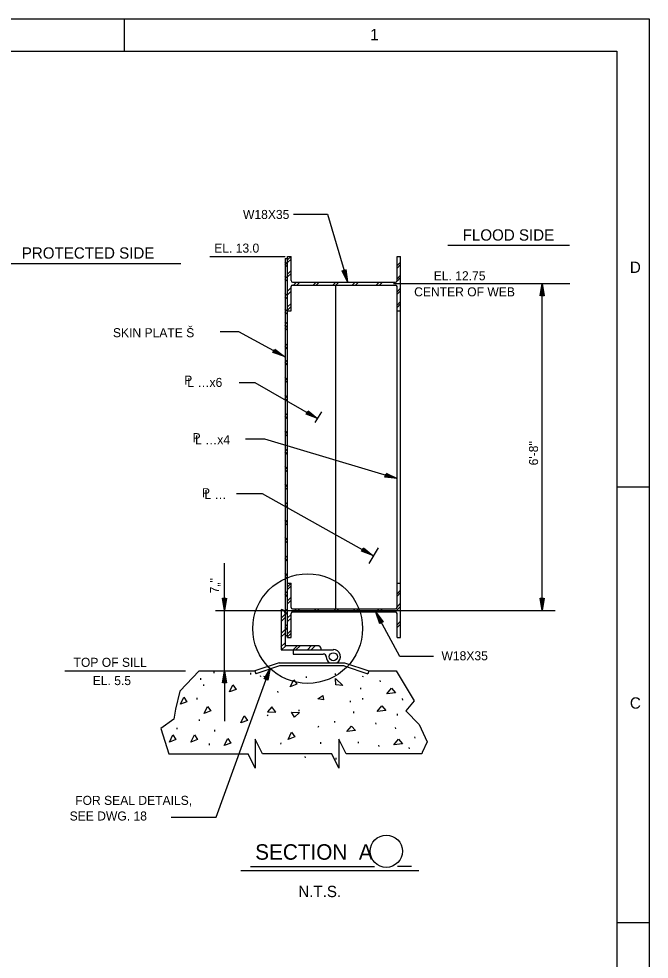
# Model space of a CAD drawing. Extents: x 0 to 53.3, y -0.3 to 37.1.
# Drawn here: x 40.32 to 53.33, y 17.66 to 37.08 of the extents above; entities that cross this region are included whole.
import ezdxf

# ---------------------------------------------------------------- set-up
doc = ezdxf.new("R2010")
doc.units = 0
for name, color, linetype in [('Level 1', 7, 'Continuous'), ('Level 2', 7, 'Continuous'), ('Level 3', 7, 'Continuous'), ('Level 44', 7, 'Continuous'), ('Level 50', 7, 'Continuous')]:
    doc.layers.add(name, color=color, linetype=linetype)

msp = doc.modelspace()

# ---------------------------------------------------------------- linework, layer by layer
at = {"layer": 'Level 1'}
for p, q in [((42.5, 36.417), (42.5, 37.083)), ((52.667, 27.417), (53.333, 27.417)), ((44.355, 23.57), (44.355, 23.6)), ((45.106, 23.543), (45.106, 23.573)), ((45.315, 23.491), (45.306, 23.512)), ((45.382, 23.491), (45.391, 23.512)), ((46.858, 23.535), (46.858, 23.563)), ((47.421, 23.491), (47.429, 23.512)), ((44.074, 23.434), (44.074, 23.464)), ((44.137, 23.307), (44.137, 23.337)), ((46.257, 23.47), (46.257, 23.5)), ((47.785, 23.386), (47.781, 23.415)), ((45.676, 23.17), (45.665, 23.194)), ((47.38, 23.235), (47.38, 23.265)), ((44.001, 23.026), (44.001, 23.056)), ((47.169, 22.969), (47.164, 22.998)), ((47.423, 23.023), (47.418, 23.052)), ((48.247, 23.014), (48.243, 23.043)), ((46.108, 22.786), (46.106, 22.808)), ((47.235, 22.745), (47.235, 22.775)), ((48.139, 22.697), (48.134, 22.726)), ((44.047, 22.582), (44.047, 22.612)), ((45.47, 22.686), (45.455, 22.711)), ((46.845, 22.546), (46.845, 22.576)), ((47.694, 22.515), (47.69, 22.544)), ((43.585, 22.41), (43.585, 22.44)), ((44.364, 22.365), (44.364, 22.395)), ((46.5, 22.452), (46.513, 22.479)), ((48.102, 22.416), (48.098, 22.445)), ((47.335, 22.12), (47.335, 22.15)), ((48.501, 22.225), (48.497, 22.254)), ((44.255, 22.084), (44.255, 22.114)), ((45.73, 22.104), (45.732, 22.128)), ((46.556, 22.111), (46.556, 22.141)), ((47.758, 22.053), (47.753, 22.082)), ((48.383, 22.007), (48.379, 22.036)), ((46.238, 21.823), (46.234, 21.846)), ((46.869, 21.788), (46.869, 21.818)), ((52.667, 18.417), (53.333, 18.417))]:
    msp.add_line(p, q, dxfattribs=at)
for points in [[(0, 37.083), (53.333, 37.083), (53.333, -0.25), (0, -0.25)], [(2, 36.417), (52.667, 36.417), (52.667, 0.417), (2, 0.417)], [(44.803, 23.233), (44.666, 23.18), (44.738, 23.327)], [(46.059, 23.339), (45.922, 23.286), (45.994, 23.434)], [(46.866, 23.326), (46.858, 23.46), (47.006, 23.315)], [(47.914, 23.142), (48.013, 23.256), (48.093, 23.162)], [(43.79, 22.978), (43.654, 22.925), (43.726, 23.072)], [(46.612, 23.021), (46.491, 23.037), (46.593, 23.105)], [(44.28, 22.787), (44.143, 22.734), (44.215, 22.882)], [(45.627, 22.765), (45.546, 22.872), (45.456, 22.769)], [(46.116, 22.754), (46.009, 22.659), (45.952, 22.765)], [(47.715, 22.779), (47.814, 22.893), (47.893, 22.799)], [(45.037, 22.594), (44.9, 22.541), (44.972, 22.688)], [(46.016, 22.253), (45.88, 22.2), (45.952, 22.348)], [(47.089, 22.362), (47.188, 22.476), (47.268, 22.382)], [(43.564, 22.197), (43.427, 22.144), (43.499, 22.292)], [(44.008, 22.198), (43.871, 22.145), (43.943, 22.293)], [(44.696, 22.126), (44.56, 22.073), (44.632, 22.22)], [(48.059, 22.09), (48.158, 22.204), (48.238, 22.11)]]:
    msp.add_lwpolyline(points, close=True, dxfattribs=at)
at = {"layer": 'Level 2'}
for p, q in [((51.686, 32.404), (49.177, 32.404)), ((45.815, 32.135), (45.867, 32.135)), ((45.815, 32.135), (45.815, 24.344)), ((45.867, 31.052), (45.867, 32.176)), ((45.867, 32.176), (45.94, 32.176)), ((45.94, 31.676), (45.94, 32.176)), ((48.128, 32.176), (48.201, 32.176)), ((48.128, 31.676), (48.128, 32.176)), ((48.201, 31.052), (48.201, 32.176)), ((48.201, 24.302), (48.201, 32.176)), ((43.663, 32.023), (40.091, 32.023)), ((45.867, 25.426), (45.867, 31.782)), ((45.94, 31.052), (45.94, 31.552)), ((45.971, 31.645), (48.096, 31.645)), ((45.971, 31.583), (48.096, 31.583)), ((46.867, 24.895), (46.867, 31.583)), ((48.128, 31.052), (48.128, 31.552)), ((48.128, 24.926), (48.128, 31.552)), ((45.867, 31.052), (45.94, 31.052)), ((48.128, 31.052), (48.201, 31.052)), ((45.867, 24.302), (45.867, 25.426)), ((45.867, 25.426), (45.94, 25.426)), ((45.94, 24.926), (45.94, 25.426)), ((48.128, 25.426), (48.201, 25.426)), ((48.201, 24.302), (48.201, 25.426)), ((45.732, 24.885), (45.732, 24.053)), ((45.971, 24.895), (48.096, 24.895)), ((45.815, 24.802), (45.815, 24.136)), ((45.94, 24.302), (45.94, 24.802)), ((45.971, 24.833), (48.096, 24.833)), ((48.128, 24.302), (48.128, 24.802)), ((45.815, 24.344), (45.867, 24.344)), ((45.867, 24.302), (45.94, 24.302)), ((48.128, 24.302), (48.201, 24.302)), ((46.481, 24.136), (45.815, 24.136)), ((45.732, 24.053), (46.814, 24.053)), ((45.981, 24.053), (45.981, 23.959)), ((45.981, 23.959), (46.605, 23.959)), ((45.691, 23.782), (45.878, 23.782)), ((47.034, 23.72), (45.701, 23.72)), ((45.878, 23.782), (47.045, 23.782)), ((43.413, 21.904), (45.051, 21.904)), ((46.779, 21.904), (45.35, 21.904)), ((48.638, 21.904), (47.078, 21.904))]:
    msp.add_line(p, q, dxfattribs=at)
msp.add_circle((46.812, 23.908), 0.0833, dxfattribs=at)
for centre, radius, start, end in [((45.971, 31.676), 0.0312, 180, 270), ((48.096, 31.676), 0.0312, 270, 0), ((45.971, 31.552), 0.0312, 90, 180), ((48.096, 31.552), 0.0312, 0, 90), ((45.732, 24.802), 0.0833, 0, 90), ((45.971, 24.926), 0.0312, 180, 270), ((48.096, 24.926), 0.0312, 270, 0), ((45.971, 24.802), 0.0312, 90, 180), ((48.096, 24.802), 0.0312, 0, 90), ((46.481, 24.053), 0.0833, 0, 90), ((46.615, 23.908), 0.052, 350.5377, 101.4263), ((46.812, 23.908), 0.146, 179.207, 240.2934), ((46.812, 23.908), 0.146, 300.1327, 92.3336)]:
    msp.add_arc(centre, radius, start, end, dxfattribs=at)
at = {"layer": 'Level 3'}
for p, q in [((44.261, 32.176), (45.815, 32.176)), ((47.082, 31.72), (47.082, 31.72)), ((47.102, 31.653), (47.102, 31.653)), ((48.057, 31.614), (51.695, 31.614)), ((51.122, 24.864), (51.122, 31.614)), ((45.743, 30.14), (45.743, 30.14)), ((45.804, 30.107), (45.804, 30.107)), ((46.427, 28.862), (46.427, 28.862)), ((46.487, 28.828), (46.487, 28.828)), ((47.569, 26.034), (47.569, 26.034)), ((47.629, 26), (47.629, 26)), ((44.38, 24.864), (51.395, 24.864)), ((47.687, 24.826), (47.687, 24.826)), ((47.72, 24.765), (47.72, 24.765)), ((45.691, 23.782), (45.191, 23.616)), ((45.701, 23.72), (45.211, 23.557)), ((47.034, 23.72), (47.525, 23.557)), ((47.045, 23.782), (47.544, 23.616)), ((41.269, 23.616), (43.762, 23.616)), ((45.191, 23.616), (45.211, 23.557)), ((47.544, 23.616), (47.525, 23.557)), ((44.904, 19.492), (48.576, 19.492)), ((45.104, 19.575), (47.663, 19.575)), ((48.428, 19.575), (48.136, 19.575))]:
    msp.add_line(p, q, dxfattribs=at)
for points in [[(45.989, 33.05), (46.692, 33.05), (47.102, 31.653)], [(47.071, 31.904), (47.102, 31.653), (46.992, 31.881), (47.06, 31.901), (47.082, 31.72), (47.008, 31.875), (47.051, 31.887), (47.064, 31.784), (47.024, 31.868), (47.041, 31.873), (47.044, 31.85)], [(44.476, 30.625), (44.857, 30.625), (45.804, 30.107)], [(45.605, 30.263), (45.804, 30.107), (45.565, 30.19), (45.599, 30.252), (45.743, 30.14), (45.581, 30.197), (45.602, 30.237), (45.684, 30.172), (45.596, 30.203), (45.605, 30.22), (45.623, 30.205)], [(44.866, 29.57), (45.189, 29.57), (46.487, 28.828)], [(46.291, 28.987), (46.487, 28.828), (46.25, 28.915), (46.285, 28.977), (46.427, 28.862), (46.266, 28.922), (46.288, 28.961), (46.369, 28.895), (46.282, 28.928), (46.291, 28.944), (46.309, 28.929)], [(44.998, 28.41), (45.388, 28.41), (48.128, 27.587)], [(44.815, 27.28), (45.34, 27.28), (47.629, 26)], [(47.432, 26.158), (47.629, 26), (47.391, 26.085), (47.426, 26.147), (47.569, 26.034), (47.407, 26.092), (47.429, 26.131), (47.51, 26.066), (47.423, 26.098), (47.432, 26.115), (47.45, 26.1)], [(48.88, 23.911), (48.187, 23.911), (47.687, 24.826)], [(47.77, 24.587), (47.687, 24.826), (47.843, 24.627), (47.781, 24.593), (47.72, 24.765), (47.826, 24.63), (47.786, 24.608), (47.752, 24.706), (47.809, 24.633), (47.793, 24.624), (47.785, 24.645)], [(43.462, 20.593), (44.395, 20.593), (45.505, 23.674)]]:
    msp.add_lwpolyline(points, dxfattribs=at)
msp.add_circle((47.906, 19.89), 0.333, dxfattribs=at)
at = {"layer": 'Level 44'}
for p, q in [((45.866, 32.01), (45.815, 32.061)), ((45.867, 32.103), (45.94, 32.176)), ((45.867, 32.047), (45.94, 32.12)), ((48.128, 31.986), (48.201, 32.059)), ((45.866, 31.954), (45.814, 32.006)), ((45.867, 31.812), (45.94, 31.885)), ((48.128, 31.936), (48.201, 32.009)), ((45.866, 31.719), (45.814, 31.771)), ((45.866, 31.658), (45.814, 31.71)), ((45.867, 31.751), (45.94, 31.824)), ((48.128, 31.715), (48.201, 31.788)), ((48.128, 31.665), (48.201, 31.738)), ((45.867, 31.458), (45.94, 31.531)), ((45.993, 31.583), (46.055, 31.645)), ((46.057, 31.583), (46.119, 31.645)), ((46.396, 31.583), (46.458, 31.645)), ((46.396, 31.583), (46.458, 31.645)), ((46.396, 31.583), (46.458, 31.645)), ((46.396, 31.583), (46.458, 31.645)), ((46.396, 31.583), (46.458, 31.645)), ((46.461, 31.583), (46.523, 31.645)), ((46.8, 31.583), (46.862, 31.645)), ((46.8, 31.583), (46.862, 31.645)), ((46.8, 31.583), (46.862, 31.645)), ((46.8, 31.583), (46.862, 31.645)), ((46.8, 31.583), (46.862, 31.645)), ((46.864, 31.583), (46.926, 31.645)), ((47.204, 31.583), (47.266, 31.645)), ((47.204, 31.583), (47.266, 31.645)), ((47.204, 31.583), (47.266, 31.645)), ((47.204, 31.583), (47.266, 31.645)), ((47.204, 31.583), (47.266, 31.645)), ((47.268, 31.583), (47.33, 31.645)), ((47.699, 31.583), (47.761, 31.645)), ((47.699, 31.583), (47.761, 31.645)), ((47.699, 31.583), (47.761, 31.645)), ((47.699, 31.583), (47.761, 31.645)), ((47.699, 31.583), (47.761, 31.645)), ((47.764, 31.583), (47.826, 31.645)), ((48.128, 31.444), (48.201, 31.517)), ((48.128, 31.394), (48.201, 31.467)), ((45.866, 31.365), (45.814, 31.417)), ((45.866, 31.291), (45.814, 31.343)), ((45.867, 31.384), (45.94, 31.457)), ((45.866, 31.041), (45.814, 31.093)), ((45.867, 31.133), (45.94, 31.206)), ((45.867, 31.068), (45.943, 31.143)), ((48.128, 31.172), (48.201, 31.245)), ((48.128, 31.123), (48.201, 31.196)), ((45.866, 30.975), (45.814, 31.027)), ((45.866, 30.774), (45.814, 30.826)), ((45.866, 30.708), (45.814, 30.76)), ((45.866, 30.702), (45.814, 30.754)), ((45.866, 30.644), (45.814, 30.696)), ((45.867, 30.328), (45.815, 30.38)), ((45.867, 30.262), (45.815, 30.314)), ((45.867, 29.99), (45.815, 30.042)), ((45.867, 29.931), (45.815, 29.983)), ((45.867, 29.622), (45.815, 29.674)), ((45.867, 29.564), (45.815, 29.616)), ((45.867, 29.255), (45.815, 29.307)), ((45.867, 29.189), (45.815, 29.241)), ((45.867, 28.887), (45.815, 28.939)), ((45.867, 28.821), (45.815, 28.873)), ((45.867, 28.52), (45.815, 28.572)), ((45.867, 28.454), (45.815, 28.506)), ((45.867, 28.152), (45.815, 28.204)), ((45.867, 28.087), (45.815, 28.139)), ((45.867, 27.785), (45.815, 27.837)), ((45.867, 27.719), (45.815, 27.771)), ((45.867, 27.418), (45.815, 27.47)), ((45.867, 27.352), (45.815, 27.404)), ((45.867, 27.05), (45.815, 27.102)), ((45.867, 26.984), (45.815, 27.036)), ((45.867, 26.683), (45.815, 26.735)), ((45.867, 26.617), (45.815, 26.669)), ((45.867, 26.315), (45.815, 26.367)), ((45.867, 26.25), (45.815, 26.302)), ((45.867, 25.948), (45.815, 26)), ((45.867, 25.882), (45.815, 25.934)), ((45.867, 25.581), (45.815, 25.633)), ((45.867, 25.515), (45.815, 25.567)), ((45.867, 25.213), (45.815, 25.265)), ((45.867, 25.353), (45.94, 25.426)), ((45.867, 25.297), (45.94, 25.37)), ((48.128, 25.209), (48.201, 25.282)), ((45.867, 25.147), (45.815, 25.199)), ((45.867, 25.062), (45.94, 25.135)), ((45.867, 25.001), (45.94, 25.074)), ((48.128, 25.159), (48.201, 25.232)), ((45.867, 24.846), (45.815, 24.898)), ((45.993, 24.833), (46.055, 24.895)), ((45.993, 24.833), (46.055, 24.895)), ((45.993, 24.833), (46.055, 24.895)), ((45.993, 24.833), (46.055, 24.895)), ((45.993, 24.833), (46.055, 24.895)), ((46.057, 24.833), (46.119, 24.895)), ((46.396, 24.833), (46.458, 24.895)), ((46.396, 24.833), (46.458, 24.895)), ((46.396, 24.833), (46.458, 24.895)), ((46.396, 24.833), (46.458, 24.895)), ((46.396, 24.833), (46.458, 24.895)), ((46.461, 24.833), (46.523, 24.895)), ((46.8, 24.833), (46.862, 24.895)), ((46.8, 24.833), (46.862, 24.895)), ((46.8, 24.833), (46.862, 24.895)), ((46.8, 24.833), (46.862, 24.895)), ((46.8, 24.833), (46.862, 24.895)), ((46.864, 24.833), (46.926, 24.895)), ((47.204, 24.833), (47.266, 24.895)), ((47.204, 24.833), (47.266, 24.895)), ((47.204, 24.833), (47.266, 24.895)), ((47.204, 24.833), (47.266, 24.895)), ((47.204, 24.833), (47.266, 24.895)), ((47.268, 24.833), (47.33, 24.895)), ((47.699, 24.833), (47.761, 24.895)), ((47.699, 24.833), (47.761, 24.895)), ((47.699, 24.833), (47.761, 24.895)), ((47.699, 24.833), (47.761, 24.895)), ((47.699, 24.833), (47.761, 24.895)), ((47.764, 24.833), (47.826, 24.895)), ((48.087, 24.833), (48.201, 24.946)), ((48.128, 24.938), (48.201, 25.011)), ((45.732, 24.706), (45.815, 24.79)), ((45.732, 24.635), (45.815, 24.718)), ((45.867, 24.78), (45.815, 24.832)), ((45.867, 24.708), (45.94, 24.781)), ((45.867, 24.634), (45.94, 24.707)), ((45.867, 24.53), (45.815, 24.582)), ((45.867, 24.464), (45.815, 24.516)), ((48.128, 24.568), (48.201, 24.641)), ((48.128, 24.51), (48.201, 24.583)), ((45.73, 24.312), (45.815, 24.397)), ((45.732, 24.385), (45.815, 24.469)), ((45.867, 24.383), (45.94, 24.456)), ((45.867, 24.318), (45.943, 24.393)), ((45.73, 24.113), (45.815, 24.198)), ((45.745, 24.052), (45.829, 24.136)), ((45.985, 24.053), (46.069, 24.136)), ((46.04, 24.052), (46.125, 24.136)), ((46.285, 24.057), (46.358, 24.13)), ((46.352, 24.053), (46.436, 24.136))]:
    msp.add_line(p, q, dxfattribs=at)
at = {"layer": 'Level 50'}
for p, q in [((51.122, 31.614), (51.122, 31.614)), ((51.122, 31.545), (51.122, 31.545)), ((46.438, 28.745), (46.572, 28.968)), ((48.061, 27.607), (48.061, 27.607)), ((48.128, 27.587), (48.128, 27.587)), ((47.736, 26.159), (47.548, 25.83)), ((44.562, 24.864), (44.562, 25.841)), ((44.562, 24.934), (44.562, 24.934)), ((44.562, 23.616), (44.562, 24.864)), ((44.562, 24.864), (44.562, 24.864)), ((51.122, 24.934), (51.122, 24.934)), ((51.122, 24.864), (51.122, 24.864)), ((44.043, 23.616), (43.644, 23.199)), ((44.043, 23.616), (45.191, 23.616)), ((44.562, 23.616), (44.562, 22.576)), ((44.562, 23.616), (44.562, 23.616)), ((44.562, 23.546), (44.562, 23.546)), ((45.481, 23.609), (45.481, 23.609)), ((45.505, 23.674), (45.505, 23.674)), ((47.544, 23.616), (48.113, 23.616)), ((48.113, 23.616), (48.484, 22.999)), ((43.644, 23.199), (43.553, 22.827)), ((48.484, 22.999), (48.312, 22.791)), ((43.553, 22.827), (43.517, 22.618)), ((48.312, 22.791), (48.584, 22.51)), ((43.517, 22.618), (43.254, 22.428)), ((43.254, 22.428), (43.413, 21.904)), ((48.584, 22.51), (48.747, 22.147)), ((45.35, 21.904), (45.201, 22.204)), ((45.201, 22.204), (45.201, 21.604)), ((47.078, 21.904), (46.929, 22.204)), ((46.929, 22.204), (46.929, 21.604)), ((48.747, 22.147), (48.647, 21.929)), ((45.201, 21.604), (45.051, 21.904)), ((46.929, 21.604), (46.779, 21.904)), ((48.647, 21.929), (48.638, 21.904))]:
    msp.add_line(p, q, dxfattribs=at)
for points in [[(51.081, 31.365), (51.122, 31.614), (51.164, 31.365), (51.093, 31.365), (51.122, 31.545), (51.15, 31.376), (51.105, 31.376), (51.122, 31.478), (51.137, 31.386), (51.118, 31.386), (51.122, 31.409)], [(47.901, 27.698), (48.128, 27.587), (47.877, 27.619), (47.897, 27.687), (48.061, 27.607), (47.891, 27.629), (47.904, 27.672), (47.997, 27.626), (47.905, 27.638), (47.91, 27.656), (47.931, 27.646)], [(44.604, 25.114), (44.562, 24.864), (44.521, 25.114), (44.592, 25.114), (44.562, 24.934), (44.534, 25.103), (44.58, 25.103), (44.562, 25), (44.548, 25.092), (44.566, 25.092), (44.562, 25.07)], [(51.164, 25.114), (51.122, 24.864), (51.081, 25.114), (51.152, 25.114), (51.122, 24.934), (51.094, 25.103), (51.14, 25.103), (51.122, 25), (51.108, 25.092), (51.126, 25.092), (51.122, 25.07)], [(44.521, 23.366), (44.562, 23.616), (44.604, 23.366), (44.533, 23.366), (44.562, 23.546), (44.59, 23.377), (44.545, 23.377), (44.562, 23.48), (44.577, 23.388), (44.558, 23.388), (44.562, 23.41)], [(45.382, 23.454), (45.505, 23.674), (45.459, 23.426), (45.393, 23.45), (45.481, 23.609), (45.45, 23.44), (45.408, 23.456), (45.459, 23.546), (45.441, 23.455), (45.424, 23.461), (45.435, 23.481)]]:
    msp.add_lwpolyline(points, dxfattribs=at)
msp.add_circle((46.283, 24.489), 1.132, dxfattribs=at)

# ---------------------------------------------------------------- texts
at = {"layer": 'Level 1'}
for s, height, p in [('1', 0.234, (47.575, 36.642)), ('D', 0.234, (52.935, 31.835)), ('C', 0.234, (52.935, 22.835)), ('N.T.S.', 0.2333, (46.09, 18.943))]:
    msp.add_text(s, height=height, dxfattribs=at).set_placement(p)
at = {"layer": 'Level 2'}
for s, height, p in [('FLOOD SIDE', 0.2333, (49.483, 32.502)), ('PROTECTED SIDE', 0.23329, (40.38, 32.13))]:
    msp.add_text(s, height=height, dxfattribs=at).set_placement(p)
at = {"layer": 'Level 3'}
for s, height, p in [('W18X35', 0.1867, (44.947, 32.949)), ('EL. 13.0', 0.1867, (44.353, 32.254)), ('W18X35', 0.1867, (49.045, 23.834)), ('TOP OF SILL', 0.1867, (41.449, 23.699)), ('FOR SEAL DETAILS,', 0.1867, (41.483, 20.848)), (' SEE DWG. 18', 0.1867, (41.299, 20.525)), ('SECTION  A', 0.32, (45.199, 19.715))]:
    msp.add_text(s, height=height, dxfattribs=at).set_placement(p)
msp.add_text("6'-8''", height=0.1867, rotation=90, dxfattribs=at).set_placement((51.039, 27.86))
at = {"layer": 'Level 50'}
for s, height, p in [('EL. 12.75', 0.1867, (48.885, 31.683)), ('CENTER OF WEB', 0.1867, (48.481, 31.351)), ('SKIN PLATE Š', 0.1867, (42.262, 30.507)), ('P', 0.187, (43.733, 29.527)), ('L …x6', 0.1867, (43.798, 29.48)), ('P', 0.187, (43.906, 28.339)), ('L …x4', 0.1867, (43.958, 28.296)), ('P', 0.187, (44.099, 27.202)), ('L …', 0.1867, (44.151, 27.166)), ('EL. 5.5', 0.1867, (41.845, 23.322))]:
    msp.add_text(s, height=height, dxfattribs=at).set_placement(p)
msp.add_text("7„''", height=0.1867, rotation=90, dxfattribs=at).set_placement((44.451, 25.218))

doc.saveas('drawing.dxf')
